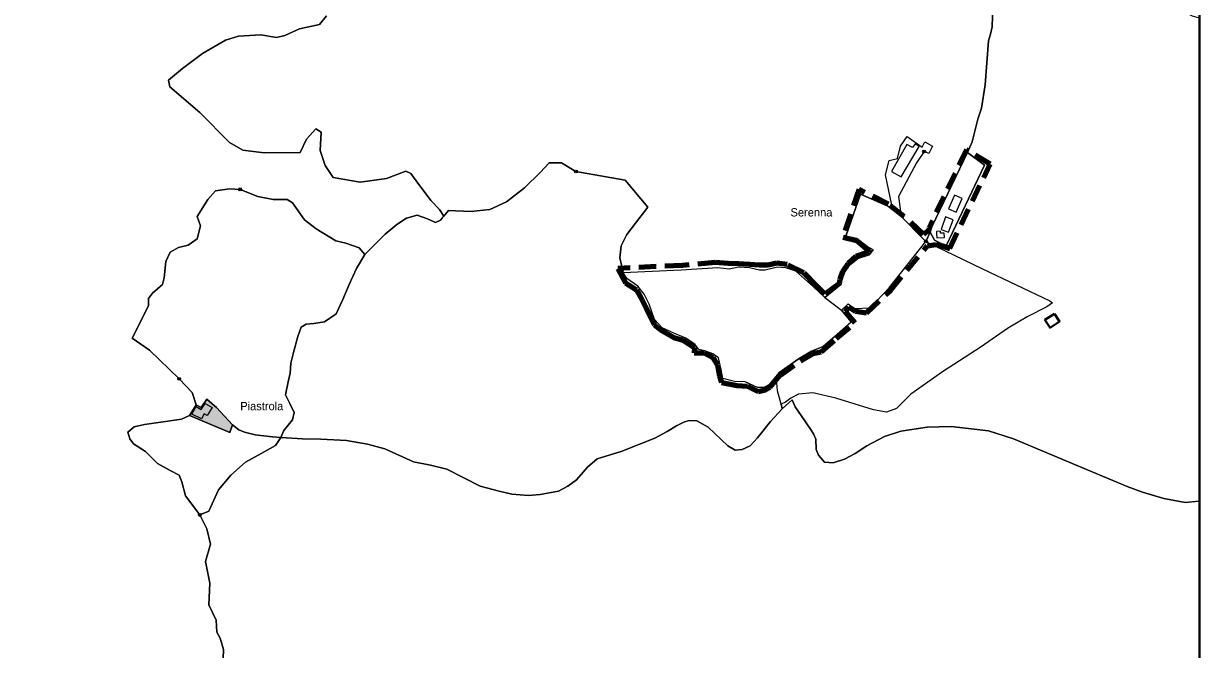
# Model space of a CAD drawing. Extents: x 650071 to 653841, y 889105 to 891996.
# Drawn here: x 652704 to 653840, y 890549 to 891152 of the extents above; entities that cross this region are included whole.
import ezdxf
from ezdxf.enums import TextEntityAlignment as Align

# ---------------------------------------------------------------- set-up
doc = ezdxf.new("R2010")
doc.units = 0
doc.header["$LTSCALE"] = 5.6
doc.header["$PDMODE"] = 32
doc.header["$PDSIZE"] = 2.8
doc.linetypes.add('MEDIUM_DASHED', pattern=[4.5, 3, -1.5])
for name, color, linetype, lineweight in [('11', 7, 'Continuous', 25), ('12', 7, 'Continuous', 25), ('3', 7, 'Continuous', 25), ('35', 7, 'Continuous', 25), ('36', 7, 'Continuous', 25), ('37', 7, 'Continuous', 25), ('4', 7, 'Continuous', 25), ('6', 7, 'Continuous', 25), ('61', 7, 'Continuous', 35), ('7', 7, 'MEDIUM_DASHED', 100), ('9', 7, 'Continuous', 25)]:
    doc.layers.add(name, color=color, linetype=linetype, lineweight=lineweight)
doc.layers.add('60', color=7, linetype='Continuous')

msp = doc.modelspace()

# ---------------------------------------------------------------- hatches: boundary and pattern name
at = {"layer": '4'}
msp.add_hatch(color=256, dxfattribs=at).paths.add_polyline_path([(652881.2, 890790.05), (652875.71, 890781.92), (652870.99, 890784.56), (652864.58, 890774.47), (652903.45, 890757.86), (652906.15, 890765.44), (652890.66, 890782.19), (652886.16, 890785.94)])

# ---------------------------------------------------------------- linework, layer by layer
at = {"layer": '11'}
msp.add_lwpolyline([(653579.82, 890951.27), (653583.92, 890943.58), (653590.49, 890940.13), (653595.23, 890937.96), (653632.33, 891016), (653615.64, 891028.21), (653581.46, 890956.31)], close=True, dxfattribs=at)
at = {"layer": '12'}
msp.add_line((653283.16, 890912.39), (653339.44, 890914.72), dxfattribs=at)
msp.add_lwpolyline([(653339.44, 890914.72), (653374.77, 890917.04), (653385.55, 890915.88), (653394.53, 890917.62), (653405.31, 890917.04), (653414.89, 890914.72), (653420.28, 890914.72), (653432.25, 890917.62), (653440.04, 890917.04), (653449.62, 890913.84), (653467.04, 890898.37), (653477.89, 890888.17), (653494.25, 890875.84), (653503.49, 890864.74), (653487.94, 890850.81), (653476.56, 890840.94), (653465.19, 890836.29), (653453.21, 890829.32), (653433.45, 890815.37), (653423.87, 890803.76), (653419.08, 890801.43), (653413.09, 890801.43), (653401.12, 890806.66), (653390.94, 890807.24), (653379.56, 890810.15), (653377.77, 890818.86), (653375.37, 890829.9), (653369.98, 890833.96), (653362.2, 890836.87), (653356.21, 890838.03), (653352.62, 890843.26), (653343.64, 890849.07), (653332.26, 890853.72), (653320.88, 890858.95), (653313.7, 890867.08), (653308.31, 890881.6), (653303.52, 890891.48), (653297.53, 890899.03), (653286.75, 890906.58), (653283.16, 890912.39)], dxfattribs=at)
at = {"layer": '3'}
for points in [[(653542.47, 890978.79), (653536.73, 891006.58), (653540.14, 891020.4), (653548.05, 891022.42), (653551, 891034.07), (653557.68, 891043.39)], [(653557.68, 891043.39), (653571.95, 891033.29), (653574.75, 891038.42), (653582.04, 891034.23), (653578.45, 891027.12), (653573.85, 891029.02)], [(653573.85, 891029.02), (653566.65, 891018.02), (653549.25, 890985.52), (653551.73, 890966.18), (653540.96, 890975.47), (653542.47, 890978.79)]]:
    msp.add_lwpolyline(points, dxfattribs=at)
msp.add_lwpolyline([(653557.36, 891035.78), (653542.47, 891009.85), (653551.62, 891004.72), (653569.16, 891033.92), (653565.12, 891036.4), (653562.8, 891032.99)], close=True, dxfattribs=at)
msp.add_point((653573.85, 891029.02), dxfattribs=at)
at = {"layer": '35'}
msp.add_lwpolyline([(653433.45, 890815.37), (653453.21, 890829.32), (653465.19, 890836.29), (653476.56, 890840.94), (653503.49, 890864.74), (653494.25, 890875.84), (653500.54, 890881.94), (653506.83, 890877.58), (653521.8, 890878.17), (653540.06, 890897.34), (653575.68, 890942.36), (653630.32, 890915.84), (653695.26, 890884.92), (653698, 890882.96), (653692.52, 890879.04), (653673.35, 890869.65), (653654.57, 890858.3), (653629.14, 890840.69), (653591.59, 890816.42), (653561.07, 890794.89), (653547.38, 890781.19), (653537.6, 890777.67), (653525.08, 890779.63), (653488.7, 890790.98), (653466.4, 890796.07), (653452.71, 890794.89), (653445.27, 890790.98), (653440.19, 890787.06), (653435.84, 890785.26), (653432.32, 890798.16), (653431.81, 890805.91)], close=True, dxfattribs=at)
at = {"layer": '36'}
for points in [[(653083.34, 891000.68), (653078.15, 891007.66), (653073.57, 891010.06), (653054.82, 891003.07), (653029.3, 890999.48), (653003.37, 891003.87), (652995.39, 891015.45), (652990.6, 891030.02), (652991.8, 891047.78), (652986.41, 891050.77), (652977.55, 891040.88), (652971.26, 891028.02), (652936.76, 891027.82), (652915.99, 891030.4), (652903.03, 891037.73), (652874.54, 891066.73), (652845.42, 891091.48), (652844.23, 891097.86), (652857.67, 891108.98), (652877.11, 891123.64), (652899.26, 891136.37), (652911.67, 891140.41), (652933.27, 891141.46), (652948.51, 891138.96), (652956.69, 891140.96), (652970.65, 891147.34), (652990.19, 891151.53), (652996.77, 891159.92)], [(653413.12, 890801.46), (653401.12, 890806.66), (653390.94, 890807.24), (653379.56, 890810.15), (653377.77, 890818.86), (653375.37, 890829.9), (653369.98, 890833.96), (653362.2, 890836.87), (653356.21, 890838.03), (653352.62, 890843.26), (653343.64, 890849.07), (653332.26, 890853.72), (653320.88, 890858.95), (653313.7, 890867.08), (653308.31, 890881.6), (653303.52, 890891.48), (653297.53, 890899.03), (653286.75, 890906.58), (653283.16, 890912.39), (653280.2, 890926.37), (653281.23, 890937.86), (653286.9, 890948.86), (653295.14, 890959.86), (653306.99, 890975.36), (653285.21, 891001.39), (653266.85, 891004.53), (653237.69, 891009.77), (653223.65, 891018.15), (653211.77, 891018.15), (653203.13, 891008.72), (653188.01, 890994.05), (653170.73, 890980.43), (653154.53, 890973.1), (653136.17, 890971), (653114.57, 890972.05), (653109.96, 890966.58), (653108.93, 890965.21), (653108.29, 890964.35)], [(653102.1, 890960.68), (653107.01, 890962.65), (653109.96, 890966.58), (653105.87, 890972.94), (653097.5, 890981.72), (653083.34, 891000.68)], [(652810.3, 890746.86), (652806.8, 890751.87), (652804.9, 890758.39), (652811.06, 890763.54), (652821.15, 890765.79), (652839.1, 890768.25), (652856.82, 890770.72), (652864.58, 890774.47), (652870.99, 890784.56), (652867, 890796.63), (652854.58, 890809.73), (652825.96, 890837.49), (652809.22, 890849.01), (652820.02, 890870.49), (652824.88, 890880.44), (652824.88, 890887.25), (652828.66, 890892.49), (652838.38, 890900.87), (652840, 890907.16), (652841.62, 890922.88), (652845.94, 890931.78), (652854.04, 890936.5), (652863.22, 890938.59), (652871.86, 890944.88), (652875.1, 890957.45), (652871.86, 890966.35), (652882.12, 890982.59), (652889.6, 890990.96), (652903.1, 890993.06), (652913.36, 890992.53)], [(652913.36, 890992.53), (652930.64, 890985.72), (652945.22, 890982.58), (652958.72, 890982.58), (652964.12, 890979.44), (652975.46, 890963.2), (652986.8, 890954.29), (653005.7, 890942.77), (653015.42, 890940.67), (653028.38, 890935.96), (653033.78, 890929.67), (653044.15, 890940.04), (653053.48, 890949.38), (653064.77, 890958.71)], [(653108.29, 890964.35), (653107.01, 890962.65), (653102.1, 890960.68), (653094.24, 890964.12), (653084.42, 890967.56), (653074.11, 890964.61), (653064.77, 890958.71), (653053.48, 890949.38), (653044.15, 890940.04), (653033.78, 890929.67), (653025.68, 890916.05), (653018.66, 890900.86), (653012.72, 890886.19), (653006.24, 890872.57), (652994.9, 890864.72), (652984.64, 890863.14)], [(653064.77, 890958.71), (653074.11, 890964.61), (653084.42, 890967.56), (653094.24, 890964.12), (653102.1, 890960.68)], [(652984.64, 890863.14), (652977.07, 890862.38), (652972.22, 890859.48), (652968.98, 890850.57), (652964.94, 890834.97), (652962.24, 890824.75), (652961.7, 890815.32), (652959.81, 890806.94), (652957.12, 890794.12), (652961.51, 890785.74), (652965.48, 890777.34), (652963.86, 890770.01), (652955.76, 890759.8), (652952.82, 890752.96)], [(653435.84, 890785.26), (653432.32, 890798.16), (653431.81, 890805.91), (653433.45, 890815.36), (653423.87, 890803.76), (653419.08, 890801.43), (653413.12, 890801.43)], [(653266.47, 890735.03), (653281.28, 890739.59), (653313.94, 890752.51), (653325.72, 890758.98), (653334.83, 890764.3), (653342.43, 890768.1), (653347.37, 890769.62), (653354.58, 890769.24), (653365.22, 890763.16), (653384.21, 890744.91), (653391.42, 890740.73), (653398.26, 890741.49), (653405.86, 890744.91), (653413.07, 890752.89), (653425.61, 890768.48), (653436.9, 890780.81), (653435.84, 890785.26)], [(653839.8, 890537.85), (653839.8, 890691.58), (653825.99, 890690.24), (653805.38, 890694.24), (653784.77, 890700.24), (653769.83, 890705.74), (653722.42, 890725.73), (653660.24, 890751.66), (653636.03, 890759.66), (653599.96, 890763.66), (653576.77, 890763.16), (653551.52, 890759.16), (653535.55, 890754.16), (653518.54, 890745.16), (653507.21, 890737.66), (653496.9, 890732.16), (653486.08, 890728.66), (653477.84, 890729.16), (653471.76, 890736.04), (653469.7, 890741.54), (653469.19, 890751.54), (653467.13, 890756.53), (653464.03, 890761.03), (653455.02, 890774.28), (653449.35, 890782.78), (653446.36, 890789.45), (653436.9, 890780.81)], [(653436.9, 890780.81), (653425.61, 890768.48), (653413.07, 890752.89), (653405.86, 890744.91), (653398.26, 890741.49), (653391.42, 890740.73), (653384.21, 890744.91), (653365.22, 890763.16), (653354.58, 890769.24), (653347.37, 890769.62), (653342.43, 890768.1), (653334.83, 890764.3), (653325.72, 890758.98), (653313.94, 890752.51), (653281.28, 890739.59), (653266.47, 890735.03)], [(653129.36, 890714.13), (653113.03, 890722.5), (653097.08, 890726.3), (653080.74, 890729.72), (653053.02, 890742.26), (653036.31, 890746.82), (653016.18, 890750.24), (652991.49, 890751.38), (652973.64, 890751.76), (652952.82, 890752.96), (652947.56, 890745.44), (652934.47, 890738.14), (652918.45, 890729.28), (652904.29, 890716.71), (652892.62, 890702.46), (652883.24, 890681.93), (652874.53, 890678.4)], [(652952.82, 890752.96), (652973.64, 890751.76), (652991.49, 890751.38), (653016.18, 890750.24), (653036.31, 890746.82), (653053.02, 890742.26), (653080.74, 890729.72), (653097.08, 890726.3), (653113.03, 890722.5), (653129.36, 890714.13)], [(652874.53, 890678.4), (652860.63, 890696.88), (652857.25, 890710.38), (652854.55, 890716.66), (652845.91, 890721.38), (652833.52, 890728.01), (652822.18, 890739.53), (652810.3, 890746.86)], [(653266.47, 890735.03), (653258.11, 890732.37), (653249, 890724.39), (653238.36, 890712.23), (653230.01, 890706.15), (653220.9, 890701.21), (653203.04, 890698.17), (653192.03, 890697.03), (653175.7, 890698.55), (653163.54, 890701.21), (653145.31, 890706.15), (653129.36, 890714.13)], [(653129.36, 890714.13), (653145.31, 890706.15), (653163.54, 890701.21), (653175.7, 890698.55), (653192.03, 890697.03), (653203.04, 890698.17), (653220.9, 890701.21), (653230.01, 890706.15), (653238.36, 890712.23), (653249, 890724.39), (653258.11, 890732.37), (653266.47, 890735.03)], [(652874.53, 890678.4), (652881.37, 890664.94), (652884.79, 890650.16)], [(652880, 890633.55), (652884.79, 890650.16), (652881.37, 890664.94), (652874.53, 890678.4)], [(652884.79, 890650.16), (652880, 890633.55), (652884.11, 890612.63), (652883.34, 890591.57), (652890.14, 890576.94)], [(652894.11, 890559.34), (652890.89, 890565.25), (652890.14, 890576.94), (652883.34, 890591.57), (652884.11, 890612.63), (652880, 890633.55)], [(652890.14, 890576.94), (652890.89, 890565.25), (652894.11, 890559.34)], [(652894.11, 890559.34), (652897.19, 890548.69), (652896.55, 890531.36), (652897.58, 890523.66), (652904.38, 890520.06), (652905.27, 890511.08)], [(652896.55, 890531.36), (652897.19, 890548.69), (652894.11, 890559.34)]]:
    msp.add_lwpolyline(points, dxfattribs=at)
for p in [(652913.36, 890992.53), (652874.53, 890678.4)]:
    msp.add_point(p, dxfattribs=at)
at = {"layer": '37'}
for points in [[(653615.64, 891028.21), (653620.37, 891038.42), (653625.8, 891060.14), (653629.32, 891070.73), (653632.85, 891093.26), (653636.1, 891135.87), (653638, 891142.39), (653639.63, 891149.45), (653639.9, 891159.49), (653639.63, 891179.85), (653640.99, 891185), (653645.06, 891190.98), (653650.75, 891196.95), (653664.86, 891209.71), (653677.88, 891222.73), (653685.48, 891234.41), (653695.52, 891246.89), (653700.13, 891251.24), (653705.01, 891253.68), (653713.97, 891255.58), (653722.68, 891257.28)], [(653722.68, 891257.28), (653713.97, 891255.58), (653705.01, 891253.68), (653700.13, 891251.24), (653695.52, 891246.89), (653685.48, 891234.41), (653677.88, 891222.73), (653664.86, 891209.71), (653650.75, 891196.95), (653645.06, 891190.98), (653640.99, 891185), (653639.63, 891179.85), (653639.9, 891159.49), (653639.63, 891149.45), (653638, 891142.39), (653636.1, 891135.87), (653632.85, 891093.26), (653629.32, 891070.73), (653625.8, 891060.14), (653620.37, 891038.42), (653615.64, 891028.21), (653632.33, 891016)], [(653722.42, 890725.73), (653769.83, 890705.74), (653784.77, 890700.24), (653805.38, 890694.24), (653825.99, 890690.24), (653835.75, 890691.19), (653839.8, 890691.58), (653839.8, 891157.64), (653833.1, 891159.64), (653820.79, 891165.63), (653791.87, 891193.27), (653766.24, 891218.93), (653734.69, 891247.89), (653722.68, 891257.28)], [(652996.77, 891159.92), (652990.19, 891151.53), (652970.65, 891147.34)], [(652970.65, 891147.34), (652956.69, 891140.96), (652948.51, 891138.96), (652933.27, 891141.46), (652911.67, 891140.41), (652899.26, 891136.37), (652877.11, 891123.64), (652857.67, 891108.98), (652844.23, 891097.86), (652845.42, 891091.48), (652874.54, 891066.73), (652903.03, 891037.73), (652915.99, 891030.4), (652936.76, 891027.82), (652971.26, 891028.02), (652977.55, 891040.88), (652986.41, 891050.77), (652991.8, 891047.78), (652990.6, 891030.02), (652995.39, 891015.45), (653003.37, 891003.87), (653029.3, 890999.48), (653054.82, 891003.07), (653073.57, 891010.06)], [(653237.69, 891009.77), (653266.85, 891004.53), (653285.21, 891001.39), (653306.99, 890975.36), (653295.14, 890959.86), (653286.9, 890948.86), (653281.23, 890937.86), (653280.2, 890926.37), (653283.16, 890912.39), (653339.44, 890914.72), (653374.77, 890917.04), (653385.55, 890915.88), (653394.53, 890917.62), (653405.31, 890917.04), (653414.89, 890914.72), (653420.28, 890914.72), (653432.25, 890917.62), (653440.04, 890917.04), (653449.62, 890913.84), (653467.04, 890898.37), (653477.89, 890888.17), (653493.66, 890901), (653494.32, 890906.27), (653496.95, 890913.51), (653503.19, 890920.42), (653509.77, 890925.86), (653520.94, 890929.48), (653524.56, 890934.09), (653518.97, 890937.38), (653508.78, 890944.94), (653498.27, 890947.25), (653512.4, 890987.72), (653540.96, 890975.47), (653542.47, 890978.79), (653536.73, 891006.58), (653540.14, 891020.4), (653548.05, 891022.42), (653551, 891034.07), (653557.68, 891043.39)], [(653557.68, 891043.39), (653571.95, 891033.29), (653574.75, 891038.42), (653582.04, 891034.23), (653578.45, 891027.12), (653573.85, 891029.02)], [(653573.85, 891029.02), (653566.65, 891018.02), (653549.25, 890985.52), (653551.73, 890966.18), (653573.29, 890944.39), (653573.34, 890944.35), (653575.68, 890942.36)], [(653575.68, 890942.36), (653579.82, 890951.27), (653581.46, 890956.31), (653615.64, 891028.21)], [(653073.57, 891010.06), (653078.15, 891007.66), (653083.34, 891000.68), (653097.5, 890981.72), (653105.87, 890972.94), (653109.96, 890966.58), (653114.57, 890972.05), (653136.17, 890971), (653154.53, 890973.1), (653170.73, 890980.43), (653188.01, 890994.05), (653203.13, 891008.72), (653211.77, 891018.15), (653223.65, 891018.15), (653237.69, 891009.77)], [(653632.33, 891016), (653595.23, 890937.96), (653590.49, 890940.13), (653583.92, 890943.58), (653579.82, 890951.27), (653575.68, 890942.36)], [(652913.36, 890992.53), (652903.1, 890993.06), (652889.6, 890990.96), (652882.12, 890982.59), (652871.86, 890966.35), (652875.1, 890957.45), (652871.86, 890944.88), (652863.22, 890938.59), (652854.04, 890936.5), (652845.94, 890931.78), (652841.62, 890922.88), (652840, 890907.16), (652838.38, 890900.87), (652828.66, 890892.49), (652824.88, 890887.25), (652824.88, 890880.44), (652820.02, 890870.49), (652809.22, 890849.01), (652825.96, 890837.49), (652854.58, 890809.73)], [(652972.22, 890859.48), (652977.07, 890862.38), (652984.64, 890863.14), (652994.9, 890864.72), (653006.24, 890872.57), (653012.72, 890886.19), (653018.66, 890900.86), (653025.68, 890916.05), (653033.78, 890929.67), (653028.38, 890935.96), (653015.42, 890940.67), (653005.7, 890942.77), (652986.8, 890954.29), (652975.46, 890963.2), (652964.12, 890979.44), (652958.72, 890982.58), (652945.22, 890982.58), (652930.64, 890985.72), (652913.36, 890992.53)], [(653575.68, 890942.36), (653630.32, 890915.84), (653695.26, 890884.92), (653698, 890882.96), (653692.52, 890879.04), (653673.35, 890869.65), (653654.57, 890858.3), (653629.14, 890840.69), (653591.59, 890816.42), (653561.07, 890794.89), (653547.38, 890781.19), (653537.6, 890777.67), (653525.08, 890779.63), (653488.7, 890790.98), (653466.4, 890796.07), (653452.71, 890794.89), (653445.27, 890790.98), (653440.19, 890787.06), (653435.84, 890785.26), (653436.9, 890780.81), (653446.36, 890789.45), (653449.35, 890782.78), (653455.02, 890774.28), (653464.03, 890761.03), (653467.13, 890756.53), (653469.19, 890751.54), (653469.7, 890741.54), (653471.76, 890736.04), (653477.84, 890729.16), (653486.08, 890728.66), (653496.9, 890732.16), (653507.21, 890737.66), (653518.54, 890745.16), (653535.55, 890754.16), (653551.52, 890759.16), (653576.77, 890763.16), (653599.96, 890763.66), (653636.03, 890759.66), (653660.24, 890751.66), (653722.42, 890725.73)], [(652906.15, 890765.44), (652912.28, 890760.48), (652917.64, 890758.23), (652927.93, 890755.83), (652944.55, 890753.72), (652952.82, 890752.96), (652955.76, 890759.8), (652963.86, 890770.01), (652965.48, 890777.34), (652961.51, 890785.74), (652957.12, 890794.12), (652959.81, 890806.94), (652961.7, 890815.32), (652962.24, 890824.75), (652964.94, 890834.97), (652968.98, 890850.57), (652972.22, 890859.48)], [(652854.58, 890809.73), (652867, 890796.63), (652870.99, 890784.56)], [(652870.99, 890784.56), (652875.71, 890781.92), (652881.2, 890790.05), (652886.16, 890785.94), (652890.66, 890782.19), (652906.15, 890765.44)], [(652906.15, 890765.44), (652903.45, 890757.86), (652864.58, 890774.47), (652856.82, 890770.72), (652839.1, 890768.25), (652821.15, 890765.79), (652811.06, 890763.54), (652804.9, 890758.39)], [(652952.82, 890752.96), (652944.55, 890753.72), (652927.93, 890755.83), (652917.64, 890758.23), (652912.28, 890760.48), (652906.15, 890765.44)], [(652804.9, 890758.39), (652806.8, 890751.87), (652810.3, 890746.86), (652822.18, 890739.53), (652833.52, 890728.01), (652845.91, 890721.38)], [(652845.91, 890721.38), (652854.55, 890716.66), (652857.25, 890710.38), (652860.63, 890696.88), (652874.53, 890678.4), (652883.24, 890681.93), (652892.62, 890702.46), (652904.29, 890716.71), (652918.45, 890729.28), (652934.47, 890738.14), (652947.56, 890745.44), (652952.82, 890752.96)]]:
    msp.add_lwpolyline(points, dxfattribs=at)
for p in [(653573.85, 891029.02), (653237.69, 891009.77), (652913.36, 890992.53), (653575.68, 890942.36), (652854.58, 890809.73)]:
    msp.add_point(p, dxfattribs=at)
at = {"layer": '4'}
for points in [[(652881.2, 890790.05), (652875.71, 890781.92), (652870.99, 890784.56), (652864.58, 890774.47), (652903.45, 890757.86), (652906.15, 890765.44), (652890.66, 890782.19), (652886.16, 890785.94)], [(652871.08, 890783.09), (652875.87, 890780.08), (652879.77, 890785.9), (652886.27, 890782), (652881.55, 890774.4), (652878.81, 890775.9), (652876.07, 890771.11), (652866.7, 890775.76)]]:
    msp.add_lwpolyline(points, close=True, dxfattribs=at)
at = {"layer": '6'}
for points in [[(653603.14, 890986.88), (653597.38, 890973.84), (653604.83, 890970.55), (653610.59, 890983.59)], [(653594.64, 890965.85), (653590.25, 890953.87), (653597.43, 890951.24), (653601.82, 890963.22)], [(653585.86, 890949.88), (653586.13, 890945.62), (653593.48, 890946.09), (653593.21, 890950.39), (653589.72, 890950.17), (653589.6, 890952.04), (653585.74, 890951.8)]]:
    msp.add_lwpolyline(points, close=True, dxfattribs=at)
at = {"layer": '6', "lineweight": 40}
msp.add_lwpolyline([(653699.75, 890872.5), (653690.54, 890866.48), (653695.47, 890858.92), (653704.68, 890864.93)], close=True, dxfattribs=at)
at = {"layer": '61', "lineweight": 40}
msp.add_lwpolyline([(653839.81, 891995.66), (653839.8, 889106.04), (652174.44, 889106.04), (652174.45, 891995.66)], close=True, dxfattribs=at)
at = {"layer": '7'}
for points in [[(653577.03, 890938.03), (653585.26, 890939.26), (653591.8, 890937.88), (653598.68, 890935.57), (653637.75, 891016.9), (653614.78, 891030.65), (653578.63, 890955.46), (653578.4, 890953.16), (653573.19, 890948.96), (653554.36, 890966.61), (653539.35, 890978.29), (653511.08, 890992.41), (653495.64, 890946.24), (653508.99, 890943.02), (653518.21, 890935.18), (653521.04, 890932.03), (653519.29, 890931.5), (653508.12, 890927.88), (653500.71, 890920.9), (653495.11, 890912.86), (653492.48, 890905.62), (653491.96, 890901.54), (653478.14, 890891.4), (653469.8, 890899.62), (653457.83, 890912.06), (653441.75, 890919.98), (653431.64, 890921.21), (653423.34, 890919.52), (653415.05, 890919.52), (653405.71, 890920.07), (653394.93, 890920.65), (653384.65, 890920.9), (653372.21, 890921.82), (653340.44, 890919.05), (653278.26, 890916.29), (653285.63, 890902.46), (653296.22, 890895.55), (653300.37, 890888.18), (653305.89, 890877.12), (653313.3, 890861.83)], [(653313.3, 890861.83), (653319.25, 890856.84), (653332.31, 890849.7), (653341.36, 890847.16), (653352.07, 890840.06), (653351.94, 890834.79), (653361.66, 890834.69), (653369.74, 890830.25), (653374.52, 890822.74), (653376.36, 890812.14), (653378.2, 890806.15), (653393.21, 890803.35), (653403.39, 890802.77), (653413.67, 890797.39), (653420.39, 890799.18), (653425.18, 890801.51), (653434.76, 890813.12), (653454.52, 890827.07), (653466.5, 890834.04), (653474.46, 890835.64), (653489.25, 890848.56), (653507.35, 890863.62), (653498.11, 890874.72), (653501.31, 890879.29), (653507.6, 890874.93), (653518.21, 890873.43), (653541.38, 890895.08), (653577.03, 890938.03)]]:
    msp.add_lwpolyline(points, dxfattribs=at)
at = {"layer": '9'}
msp.add_lwpolyline([(653573.34, 890944.35), (653573.29, 890944.39), (653551.73, 890966.18), (653540.96, 890975.47), (653512.4, 890987.72), (653498.27, 890947.25), (653508.78, 890944.94), (653518.97, 890937.38), (653524.56, 890934.09), (653520.94, 890929.48), (653509.77, 890925.86), (653503.19, 890920.42), (653496.95, 890913.51), (653494.32, 890906.27), (653493.66, 890901), (653477.89, 890888.17), (653494.25, 890875.84), (653500.54, 890881.94), (653506.83, 890877.58), (653521.8, 890878.17), (653540.06, 890897.34), (653575.68, 890942.36)], close=True, dxfattribs=at)

# ---------------------------------------------------------------- texts
at = {"layer": '60'}
for s, p in [('Serenna', (653465.11, 890966.34)), ('Piastrola', (652934.32, 890779.4))]:
    msp.add_text(s, height=8, dxfattribs=at).set_placement(p, align=Align.CENTER)

doc.saveas('drawing.dxf')
